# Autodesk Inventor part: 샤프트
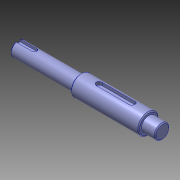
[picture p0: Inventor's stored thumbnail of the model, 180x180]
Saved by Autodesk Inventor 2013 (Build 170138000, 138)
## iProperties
Created: 2013-07
Part Number: 샤프트
Document SubType Name: Modeling
Designer: SeoGD™[esajin.kr]
Density: 7.86 g/cm^3
Mass: 291.771 g
Surface Area: 92.3634 cm^2
Volume: 37.1209 cm^3
Material: 강철, 연강
Author: SeoGD™[esajin.kr]
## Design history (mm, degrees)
sketch "스케치1"
  geometry: L1 (48, 37.7)-(48, 10.3) reference; L2 (35, 9.938)-(35, 54) reference; L3 (-35, 54)-(-35, 9.938) reference; L4 (-48, 37.7)-(-48, 10.3) reference; L5 (-70, 6.645)-(-70, 41.355) reference; L6 (-100, 24)-(49, 24); L7 (49, 24)-(49, 31.5); L8 (49, 31.5)-(35, 31.5); L9 (35, 31.5)-(35, 34.5); L10 (35, 34.5)-(-35, 34.5); L11 (-35, 34.5)-(-35, 31.5); L12 (-35, 31.5)-(-100, 31.5); L13 (-100, 31.5)-(-100, 24); 2 further points
  constraints: 16 end point, 5 perpendicular, 5 point on line, 1 collinear, 1 midpoint, 1 parallel
  dimensions: "d1" = 15 diameter of L12 L6; "d2" = 21 diameter of L10 L6; "d3" = 1 distance between parallel lines of L7 L1; "d4" = 30 distance between parallel lines of L13 L5
revolve "회전1" sketch "스케치1" stored, may be unused: angle "d5" = 90 deg
node "작업 평면1"
sketch "스케치2"
  geometry: L1 (35, -10.5)-(35, 10.5) reference; L2 (-16, -3)-(18, -3); L3 (18, 3)-(-16, 3); A1 r 3 centre (18, 0) between (18, -3) and (18, 3); A2 r 3 centre (-16, 0) between (-16, 3) and (-16, -3); 2 further points
  constraints: 4 end point, 4 point on circle, 4 tangent, 2 centre point, 1 horizontal alignment, 1 midpoint, 1 parallel, 1 perpendicular
  dimensions: "d6" = 6 distance between parallel lines of L2 L3; "d7" = 40 dimension on A1 A2; "d8" = 14 distance edge to line of A1 L1
extrude "돌출1" cut sketch "스케치2" distance "d9" = 3.5; taper "d10" = 0 deg
chamfer "모따기1" distance "d11" = 1; stored, may be unused: second distance "d12" = 2, angle "d13" = 45 deg
node "작업 평면2"
sketch "스케치3"
  geometry: L1 (-32.5, -6.5)-(-32.5, 6.5) reference; L2 (-32.5, 2.5)-(-15, 2.5); L3 (-15, -2.5)-(-32.5, -2.5); A1 r 2.5 centre (-15, 0) between (-15, -2.5) and (-15, 2.5); 2 further points
  constraints: 4 end point, 2 perpendicular, 2 point on circle, 2 point on line, 2 tangent, 1 centre point, 1 horizontal alignment, 1 midpoint
  dimensions: "d14" = 5 distance between parallel lines of L3 L2; "d15" = 20 dimension on A1 L1
extrude "돌출2" cut sketch "스케치3" distance "d16" = 3; taper "d17" = 0 deg
node "솔리드1"
node "참조1"
node "참조2"
node "참조3"
node "참조4"
node "참조5"
